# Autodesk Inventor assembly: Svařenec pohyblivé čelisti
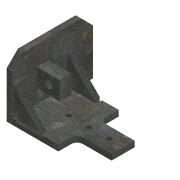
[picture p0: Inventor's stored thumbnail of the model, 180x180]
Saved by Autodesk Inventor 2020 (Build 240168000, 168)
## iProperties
Created: 2025-03
Part Number: Svařenec pohyblivé čelisti
Document SubType Name: Assembly
Designer: doma
Mass: 2326.4 g
Surface Area: 741.867 cm^2
Volume: 296.356 cm^3
Density: 7.85 g/cm^3
Author: doma
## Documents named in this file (5)
- C:\Users\doma\Desktop\Pásovka záloha\Workgroups\NotInProject\Svařenec pohyblivé čelisti.iam
- C:\Users\doma\Desktop\Pásovka záloha\Workgroups\NotInProject\Jezdec čelisti.ipt
- C:\Users\doma\Desktop\Pásovka záloha\Workgroups\NotInProject\Pohyblivá čelist.ipt
- C:\Users\doma\Desktop\Pásovka záloha\Workgroups\NotInProject\Výztuha pohyblivé čelisti.ipt
- C:\Users\doma\Desktop\Pásovka záloha\Workgroups\NotInProject\Zajištění pohyblivé čelisti 2.ipt
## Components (5 placed, 4 different names)
1. Jezdec čelisti:1 — Proti sobě:1, Stejný směr:1, Stejný směr:2, Proti sobě:2, Stejný směr:3, Proti sobě:4, Stejný směr:4, Proti sobě:6, Stejný směr:5
2. Pohyblivá čelist:1 — Proti sobě:1, Stejný směr:1, Stejný směr:2, Proti sobě:3, Proti sobě:5, Proti sobě:7
3. Výztuha pohyblivé čelisti:1 — Proti sobě:4, Proti sobě:5, Stejný směr:4
4. Výztuha pohyblivé čelisti:2 — Proti sobě:2, Proti sobě:3, Stejný směr:3
5. Zajištění pohyblivé čelisti 2:1 — Proti sobě:6, Stejný směr:5, Proti sobě:7
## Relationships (12: Mate 7, Flush 5)
- Proti sobě:1 [Mate]: Jezdec čelisti:1 ↔ Pohyblivá čelist:1
- Stejný směr:1 [Flush]: Jezdec čelisti:1 ↔ Pohyblivá čelist:1
- Stejný směr:2 [Flush]: Jezdec čelisti:1 ↔ Pohyblivá čelist:1
- Proti sobě:2 [Mate]: Jezdec čelisti:1 ↔ Výztuha pohyblivé čelisti:2
- Proti sobě:3 [Mate]: Pohyblivá čelist:1 ↔ Výztuha pohyblivé čelisti:2
- Stejný směr:3 [Flush]: Jezdec čelisti:1 ↔ Výztuha pohyblivé čelisti:2
- Proti sobě:4 [Mate]: Jezdec čelisti:1 ↔ Výztuha pohyblivé čelisti:1
- Proti sobě:5 [Mate]: Pohyblivá čelist:1 ↔ Výztuha pohyblivé čelisti:1
- Stejný směr:4 [Flush]: Jezdec čelisti:1 ↔ Výztuha pohyblivé čelisti:1
- Proti sobě:6 [Mate]: Jezdec čelisti:1 ↔ Zajištění pohyblivé čelisti 2:1
- Stejný směr:5 [Flush]: Jezdec čelisti:1 ↔ Zajištění pohyblivé čelisti 2:1
- Proti sobě:7 [Mate]: Pohyblivá čelist:1 ↔ Zajištění pohyblivé čelisti 2:1
